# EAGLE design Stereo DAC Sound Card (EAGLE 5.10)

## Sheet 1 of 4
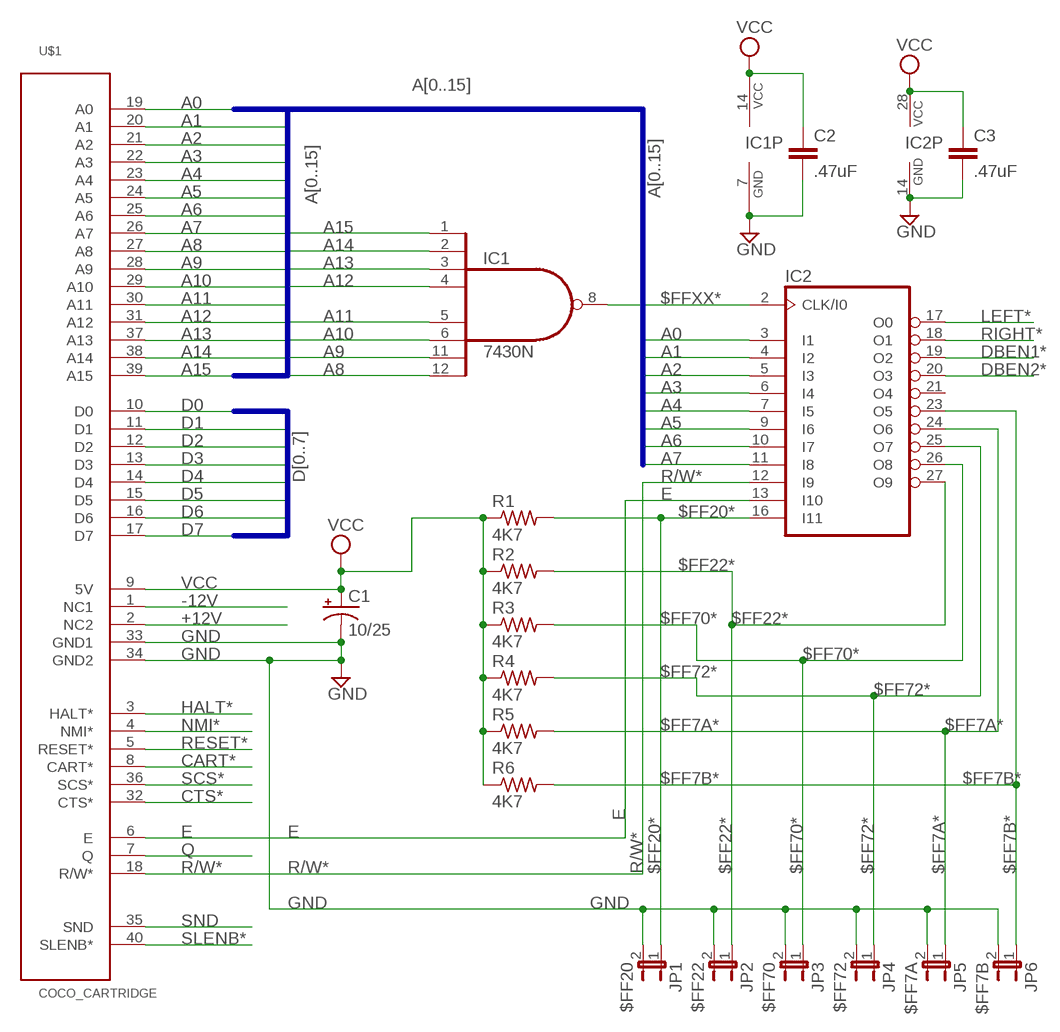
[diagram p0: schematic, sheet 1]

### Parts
C1  10/25  CAP_POLPTH1  [CPOL-RADIAL-100UF-25V]
C2  .47uF  CAPPTH2  [CAP-PTH-SMALL2]
C3  .47uF  CAPPTH2  [CAP-PTH-SMALL2]
IC1  7430N  [DIL14]
IC2  22V10L-5  [S28]
JP1  $FF20  JP1E  [JP1]
JP2  $FF22  JP1E  [JP1]
JP3  $FF70  JP1E  [JP1]
JP4  $FF72  JP1E  [JP1]
JP5  $FF7A  JP1E  [JP1]
JP6  $FF7B  JP1E  [JP1]
R1  4K7  R-US_0207/10  [0207/10]
R2  4K7  R-US_0207/10  [0207/10]
R3  4K7  R-US_0207/10  [0207/10]
R4  4K7  R-US_0207/10  [0207/10]
R5  4K7  R-US_0207/10  [0207/10]
R6  4K7  R-US_0207/10  [0207/10]
U$1  COCO_CARTRIDGE  SERIALTECH_COCO_CARTRIDGE  [SERIALTECH_EDGE40]

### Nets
$FF7A*: IC2.24(O6) JP5.1 R5.2
$FF7B*: IC2.23(O5) JP6.1 R6.2
$FF20*: IC2.16(I11) JP1.1 R1.2
$FF22*: IC2.27(O9) JP2.1 R2.2
$FF70*: IC2.26(O8) JP3.1 R3.2
$FF72*: IC2.25(O7) JP4.1 R4.2
$FFXX*: IC1.8(O) IC2.2(CLK/I0)
+12V [power]: U$1.2(NC2) ; also sheet 3
-12V [power]: U$1.1(NC1) ; also sheet 3
A0: IC2.3(I1) U$1.19(A0) ; also sheet 3
A1: IC2.4(I2) U$1.20(A1) ; also sheet 3
A2: IC2.5(I3) U$1.21(A2) ; also sheet 3
A3: IC2.6(I4) U$1.22(A3) ; also sheet 3
A4: IC2.7(I5) U$1.23(A4) ; also sheet 3
A5: IC2.9(I6) U$1.24(A5) ; also sheet 3
A6: IC2.10(I7) U$1.25(A6) ; also sheet 3
A7: IC2.11(I8) U$1.26(A7) ; also sheet 3
A8: IC1.12(I7) U$1.27(A8) ; also sheet 3
A9: IC1.11(I6) U$1.28(A9) ; also sheet 3
A10: IC1.6(I5) U$1.29(A10) ; also sheet 3
A11: IC1.5(I4) U$1.30(A11) ; also sheet 3
A12: IC1.4(I3) U$1.31(A12) ; also sheet 3
A13: IC1.3(I2) U$1.37(A13) ; also sheet 3
A14: IC1.2(I1) U$1.38(A14) ; also sheet 3
A15: IC1.1(I0) U$1.39(A15) ; also sheet 3
CART*: U$1.8(CART*) ; also sheet 3
CTS*: U$1.32(CTS*) ; also sheet 3
D0: U$1.10(D0) ; also sheet 2,3
D1: U$1.11(D1) ; also sheet 2,3
D2: U$1.12(D2) ; also sheet 2,3
D3: U$1.13(D3) ; also sheet 2,3
D4: U$1.14(D4) ; also sheet 2,3
D5: U$1.15(D5) ; also sheet 2,3
D6: U$1.16(D6) ; also sheet 2,3
D7: U$1.17(D7) ; also sheet 2,3
DBEN1*: IC2.19(O2) ; also sheet 2
DBEN2*: IC2.20(O3) ; also sheet 2
E: IC2.13(I10) U$1.6(E) ; also sheet 3
GND [power]: C1.2(-) C2.2 C3.2 IC1.7(GND) IC2.14(GND) JP1.2 JP2.2 JP3.2 JP4.2 JP5.2 JP6.2 U$1.33(GND1) U$1.34(GND2) ; also sheet 2,3,4
HALT*: U$1.3(HALT*) ; also sheet 3
LEFT*: IC2.17(O0) ; also sheet 4
NMI*: U$1.4(NMI*) ; also sheet 3
Q: U$1.7(Q) ; also sheet 3
R/W*: IC2.12(I9) U$1.18(R/W*) ; also sheet 3
RESET*: U$1.5(RESET*) ; also sheet 3
RIGHT*: IC2.18(O1) ; also sheet 4
SCS*: U$1.36(SCS*) ; also sheet 3
SLENB*: U$1.40(SLENB*) ; also sheet 3
SND: U$1.35(SND) ; also sheet 3
VCC [power]: C1.1(+) C2.1 C3.1 IC1.14(VCC) IC2.28(VCC) R1.1 R2.1 R3.1 R4.1 R5.1 R6.1 U$1.9(5V) ; also sheet 2,3,4
Unconnected: IC2.21(O4)

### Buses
A[0..15]
D[0..7]

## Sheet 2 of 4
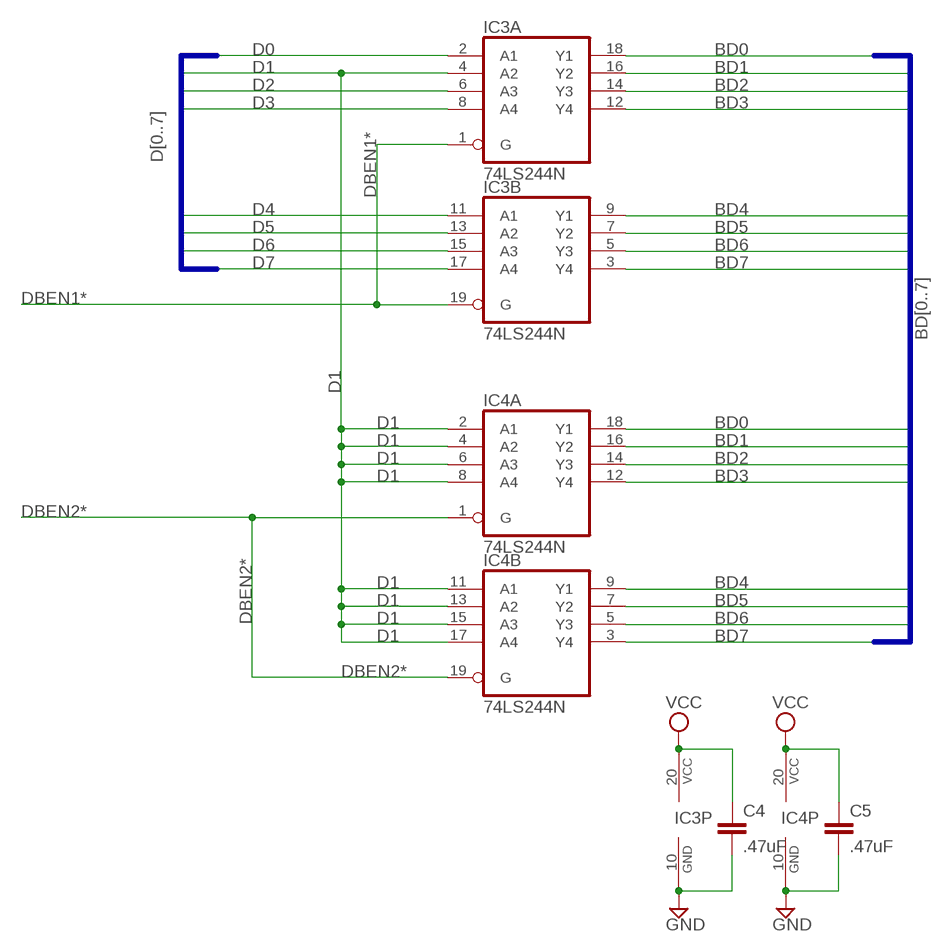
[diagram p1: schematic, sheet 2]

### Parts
C4  .47uF  CAPPTH2  [CAP-PTH-SMALL2]
C5  .47uF  CAPPTH2  [CAP-PTH-SMALL2]
IC3  74LS244N  [DIL20]
IC4  74LS244N  [DIL20]

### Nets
BD0: IC3.18(A:Y1) IC4.18(A:Y1) ; also sheet 4
BD1: IC3.16(A:Y2) IC4.16(A:Y2) ; also sheet 4
BD2: IC3.14(A:Y3) IC4.14(A:Y3) ; also sheet 4
BD3: IC3.12(A:Y4) IC4.12(A:Y4) ; also sheet 4
BD4: IC3.9(B:Y1) IC4.9(B:Y1) ; also sheet 4
BD5: IC3.7(B:Y2) IC4.7(B:Y2) ; also sheet 4
BD6: IC3.5(B:Y3) IC4.5(B:Y3) ; also sheet 4
BD7: IC3.3(B:Y4) IC4.3(B:Y4) ; also sheet 4
D0: IC3.2(A:A1) ; also sheet 1,3
D1: IC3.4(A:A2) IC4.2(A:A1) IC4.4(A:A2) IC4.6(A:A3) IC4.8(A:A4) IC4.11(B:A1) IC4.13(B:A2) IC4.15(B:A3) IC4.17(B:A4) ; also sheet 1,3
D2: IC3.6(A:A3) ; also sheet 1,3
D3: IC3.8(A:A4) ; also sheet 1,3
D4: IC3.11(B:A1) ; also sheet 1,3
D5: IC3.13(B:A2) ; also sheet 1,3
D6: IC3.15(B:A3) ; also sheet 1,3
D7: IC3.17(B:A4) ; also sheet 1,3
DBEN1*: IC3.1(A:G) IC3.19(B:G) ; also sheet 1
DBEN2*: IC4.1(A:G) IC4.19(B:G) ; also sheet 1
GND [power]: C4.2 C5.2 IC3.10(P:GND) IC4.10(P:GND) ; also sheet 1,3,4
VCC [power]: C4.1 C5.1 IC3.20(P:VCC) IC4.20(P:VCC) ; also sheet 1,3,4

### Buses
D[0..7]
BD[0..7]

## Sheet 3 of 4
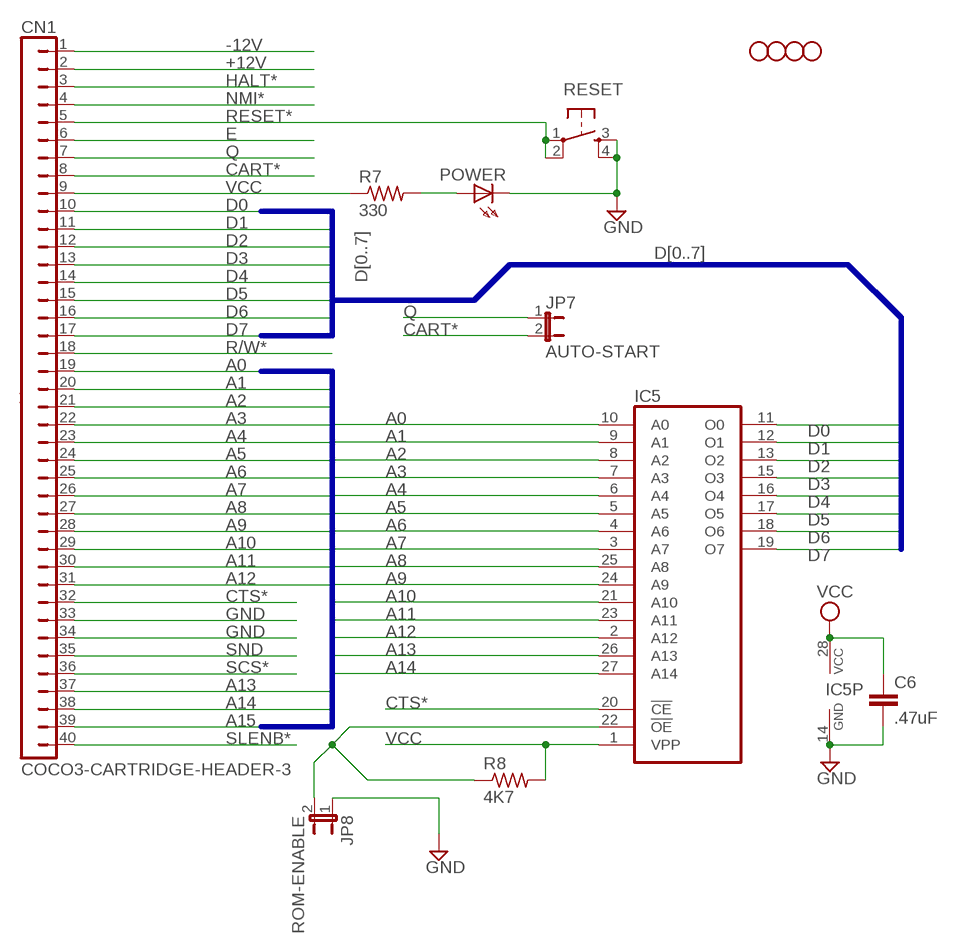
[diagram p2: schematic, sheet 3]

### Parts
C6  .47uF  CAPPTH2  [CAP-PTH-SMALL2]
CN1  COCO3-CARTRIDGE-HEADER-3  [HEADER-40]
IC5  27256  [DIL28]
JP7  AUTO-START  JP1E  [JP1]
JP8  ROM-ENABLE  JP1E  [JP1]
POWER  LED_LED5MM  [LED_LED5MM]
R7  330  R-US_0207/10  [0207/10]
R8  4K7  R-US_0207/10  [0207/10]
RESET  RESET  TAC_SWITCHPTH  [TACTILE-PTH]
U$2  SPARKFUN_STAND-OFF  [SPARKFUN_STAND-OFF]
U$3  SPARKFUN_STAND-OFF  [SPARKFUN_STAND-OFF]
U$4  SPARKFUN_STAND-OFF  [SPARKFUN_STAND-OFF]
U$5  SPARKFUN_STAND-OFF  [SPARKFUN_STAND-OFF]

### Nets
+12V [power]: CN1.2 ; also sheet 1
-12V [power]: CN1.1 ; also sheet 1
A0: CN1.19 IC5.10(A0) ; also sheet 1
A1: CN1.20 IC5.9(A1) ; also sheet 1
A2: CN1.21 IC5.8(A2) ; also sheet 1
A3: CN1.22 IC5.7(A3) ; also sheet 1
A4: CN1.23 IC5.6(A4) ; also sheet 1
A5: CN1.24 IC5.5(A5) ; also sheet 1
A6: CN1.25 IC5.4(A6) ; also sheet 1
A7: CN1.26 IC5.3(A7) ; also sheet 1
A8: CN1.27 IC5.25(A8) ; also sheet 1
A9: CN1.28 IC5.24(A9) ; also sheet 1
A10: CN1.29 IC5.21(A10) ; also sheet 1
A11: CN1.30 IC5.23(A11) ; also sheet 1
A12: CN1.31 IC5.2(A12) ; also sheet 1
A13: CN1.37 IC5.26(A13) ; also sheet 1
A14: CN1.38 IC5.27(A14) ; also sheet 1
A15: CN1.39 ; also sheet 1
CART*: CN1.8 JP7.2 ; also sheet 1
CTS*: CN1.32 IC5.20(!CE) ; also sheet 1
D0: CN1.10 IC5.11(O0) ; also sheet 1,2
D1: CN1.11 IC5.12(O1) ; also sheet 1,2
D2: CN1.12 IC5.13(O2) ; also sheet 1,2
D3: CN1.13 IC5.15(O3) ; also sheet 1,2
D4: CN1.14 IC5.16(O4) ; also sheet 1,2
D5: CN1.15 IC5.17(O5) ; also sheet 1,2
D6: CN1.16 IC5.18(O6) ; also sheet 1,2
D7: CN1.17 IC5.19(O7) ; also sheet 1,2
E: CN1.6 ; also sheet 1
GND [power]: C6.2 CN1.33 CN1.34 IC5.14(GND) JP8.1 POWER.K(C) RESET.3 RESET.4 ; also sheet 1,2,4
HALT*: CN1.3 ; also sheet 1
N$1: POWER.A R7.2
N$2: IC5.22(!OE) JP8.2 R8.1
NMI*: CN1.4 ; also sheet 1
Q: CN1.7 JP7.1 ; also sheet 1
R/W*: CN1.18 ; also sheet 1
RESET*: CN1.5 RESET.1 RESET.2 ; also sheet 1
SCS*: CN1.36 ; also sheet 1
SLENB*: CN1.40 ; also sheet 1
SND: CN1.35 ; also sheet 1
VCC [power]: C6.1 CN1.9 IC5.1(VPP) IC5.28(VCC) R7.1 R8.2 ; also sheet 1,2,4

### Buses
A[0..15]
D[0..7]

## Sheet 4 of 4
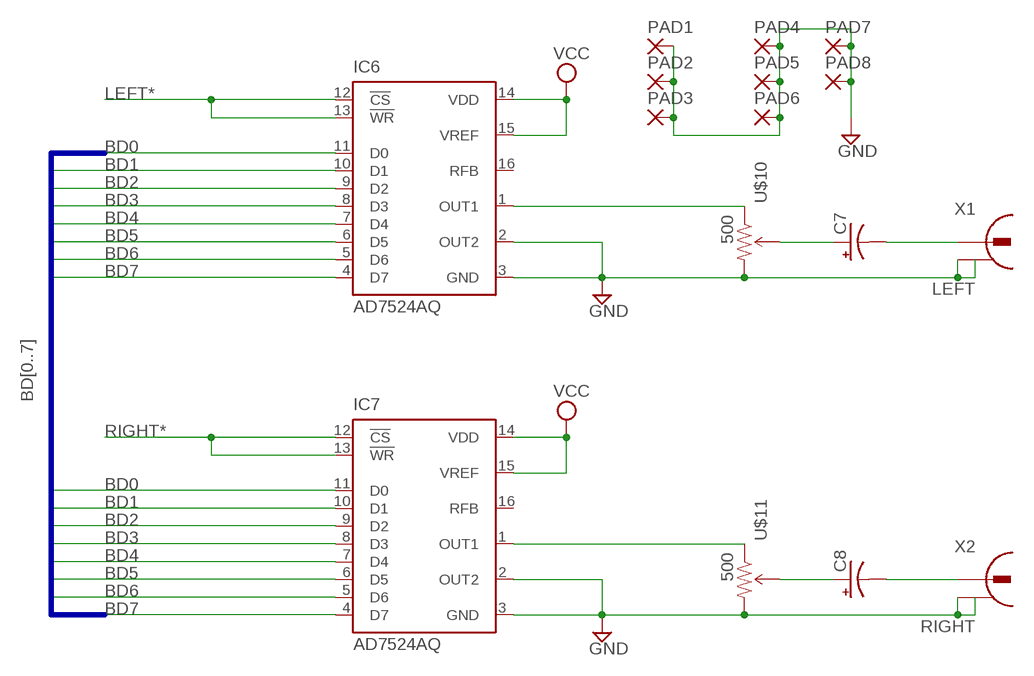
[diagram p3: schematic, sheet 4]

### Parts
C7  CAP_POLPTH2  [CPOL-RADIAL-10UF-25V]
C8  CAP_POLPTH2  [CPOL-RADIAL-10UF-25V]
IC6  AD7524AQ  [DIL16]
IC7  AD7524AQ  [DIL16]
PAD1  3,81/1,4  [3,81/1,4]
PAD2  3,81/1,4  [3,81/1,4]
PAD3  3,81/1,4  [3,81/1,4]
PAD4  3,81/1,4  [3,81/1,4]
PAD5  3,81/1,4  [3,81/1,4]
PAD6  3,81/1,4  [3,81/1,4]
PAD7  3,81/1,4  [3,81/1,4]
PAD8  3,81/1,4  [3,81/1,4]
U$10  500  TRIMPOT  [3362U-2]
U$11  500  TRIMPOT  [3362U-2]
X1  LEFT  736880-49  [736880-49]
X2  RIGHT  736880-49  [736880-49]

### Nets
BD0: IC6.11(D0) IC7.11(D0) ; also sheet 2
BD1: IC6.10(D1) IC7.10(D1) ; also sheet 2
BD2: IC6.9(D2) IC7.9(D2) ; also sheet 2
BD3: IC6.8(D3) IC7.8(D3) ; also sheet 2
BD4: IC6.7(D4) IC7.7(D4) ; also sheet 2
BD5: IC6.6(D5) IC7.6(D5) ; also sheet 2
BD6: IC6.5(D6) IC7.5(D6) ; also sheet 2
BD7: IC6.4(D7) IC7.4(D7) ; also sheet 2
GND [power]: IC6.2(OUT2) IC6.3(GND) IC7.2(OUT2) IC7.3(GND) PAD1.1(P) PAD2.1(P) PAD3.1(P) PAD4.1(P) PAD5.1(P) PAD6.1(P) PAD7.1(P) PAD8.1(P) U$10.3(CW) U$11.3(CW) X1.2 X1.2@2 X2.2 X2.2@2 ; also sheet 1,2,3
LEFT*: IC6.12(!CS) IC6.13(!WR) ; also sheet 1
N$3: IC7.1(OUT1) U$11.1(CCW)
N$4: C8.1(+) U$11.2(WIPER)
N$5: IC6.1(OUT1) U$10.1(CCW)
N$6: C8.2(-) X2.1
N$7: C7.1(+) U$10.2(WIPER)
N$8: C7.2(-) X1.1
RIGHT*: IC7.12(!CS) IC7.13(!WR) ; also sheet 1
VCC [power]: IC6.14(VDD) IC6.15(VREF) IC7.14(VDD) IC7.15(VREF) ; also sheet 1,2,3
Unconnected: IC6.16(RFB) IC7.16(RFB)

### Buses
BD[0..7]

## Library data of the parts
C1 C7 C8 = SparkFunEagle-6-6-07:CAP_POL: Capacitor Polarized
C2-C6 = SparkFunEagle-6-6-07:CAP: Capacitor
CN1 = GIMEchip:COCO3-CARTRIDGE-HEADER-3
IC1 = 74xx-us:74*30: 8-input NAND gate
IC2 = pld-intel:22V10L-5: PLD
IC3 IC4 = 74xx-us:74*244: Octal BUFFER and LINE DRIVER, 3-state
IC5 = memory:27256: MEMORY
IC6 IC7 = analog-devices:AD7524*: 8-Bit Buffered Multiplying DAC Source: http://www.analog.com/UploadedFiles/Data_Sheets/888358036ad7524.pdf
JP1-JP8 = jumper:JP1E: JUMPER
PAD1-PAD8 = wirepad:3,81/1,4: THROUGH-HOLE PAD
POWER = ZX15-004:LED_LED: LED
R1-R8 = rcl:R-US_: RESISTOR, American symbol
RESET = SparkFunEagle-6-6-07:TAC_SWITCH: Momentary Switch Button commonly used for reset or general input. Spark Fun Electronics SKU : COM-00097
U$1 = FDC:SERIALTECH_COCO_CARTRIDGE
U$2-U$5 = FDC:SPARKFUN_STAND-OFF: Stand Off
U$10 U$11 = SparkFun:TRIMPOT
X1 X2 = con-conrad:736880-49: Cinch Connector ( RCA Jack )

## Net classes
0 default: width 0.203 mm, clearance 0.203 mm
1 power: width 0.762 mm, clearance 0.381 mm

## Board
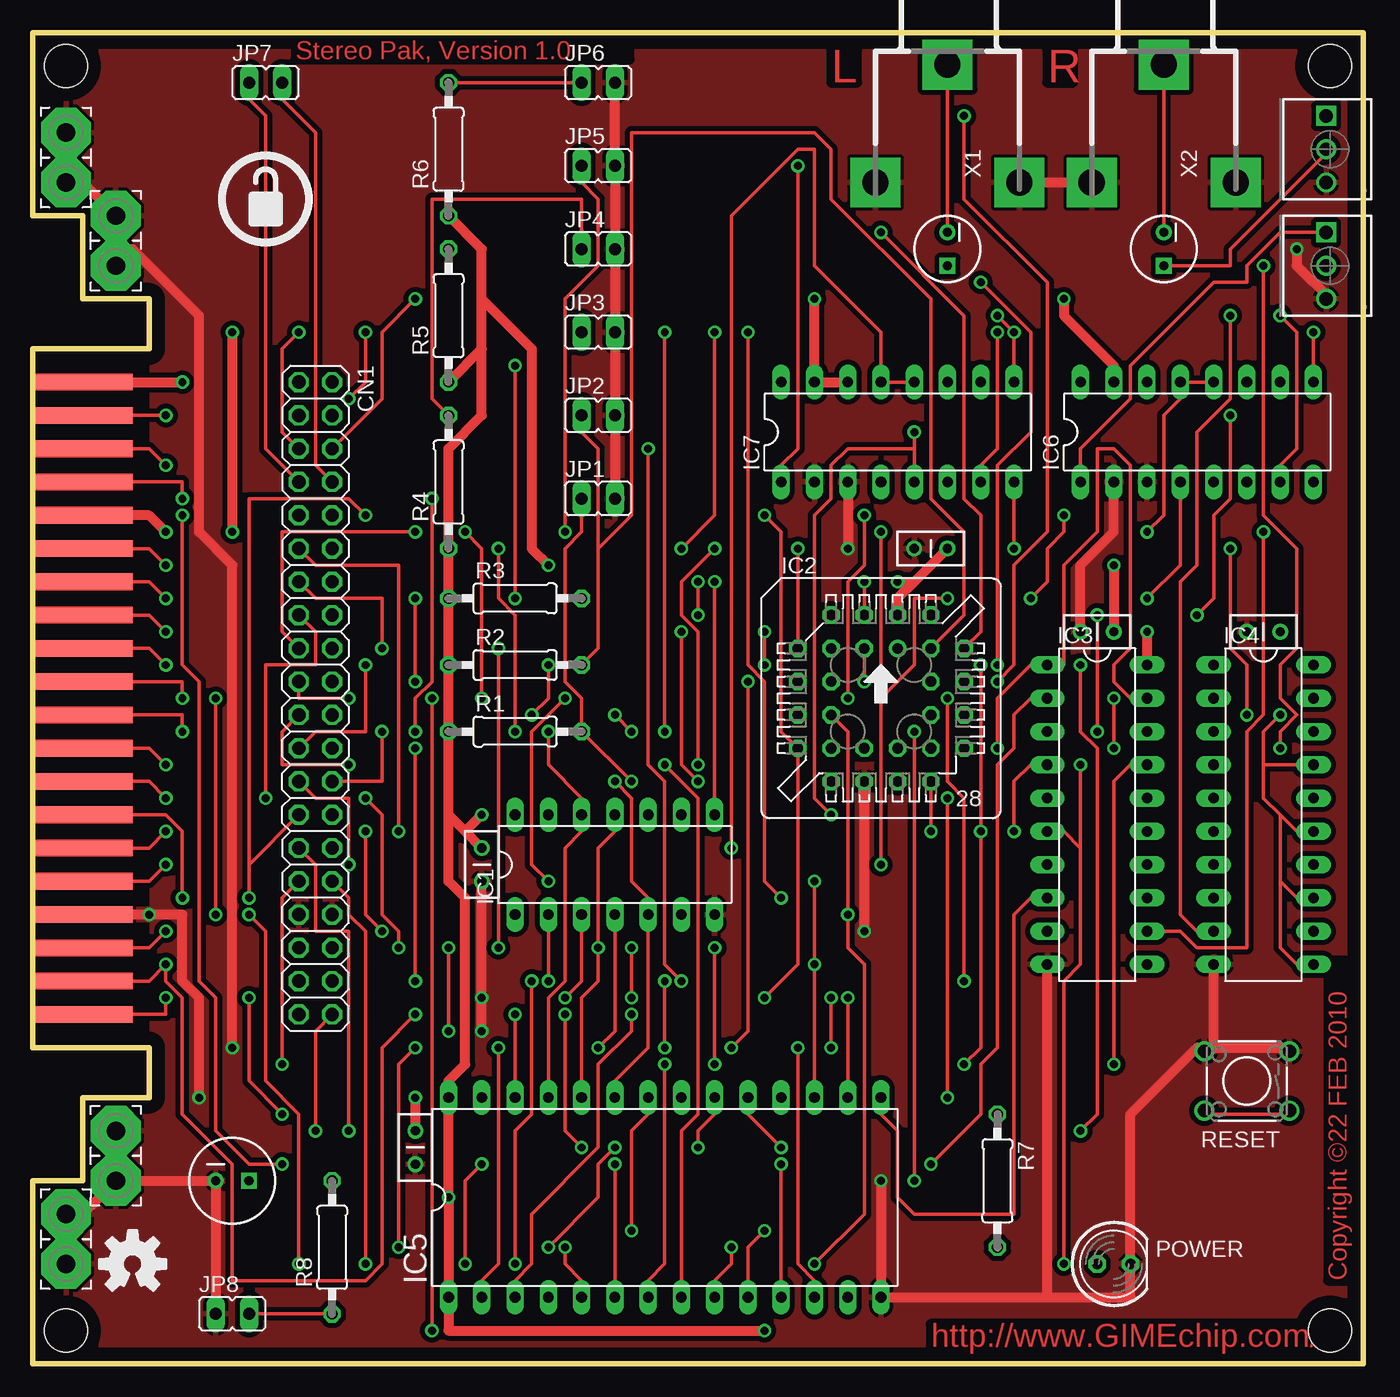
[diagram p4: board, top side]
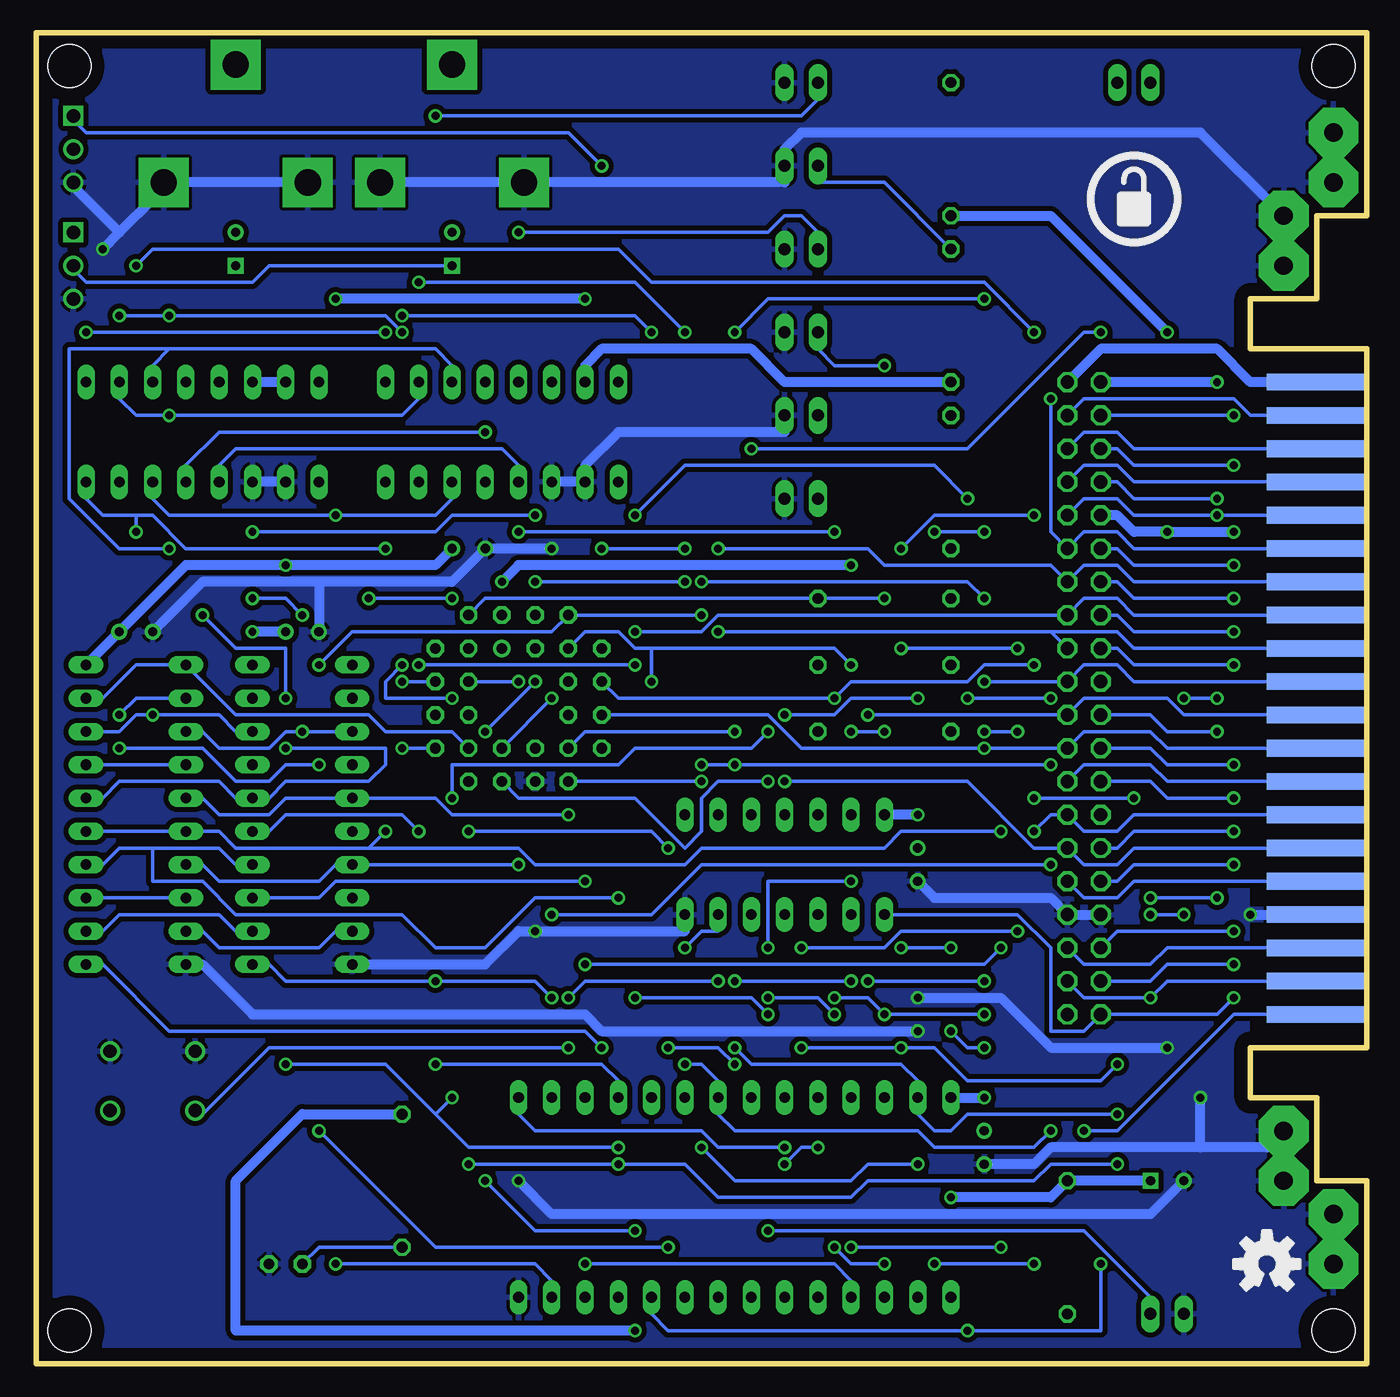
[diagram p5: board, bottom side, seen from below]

Size 101.6 x 101.6 mm. Coordinates in mm from the lower left corner, seen from the top.
Outline: 8.89,24.13 0,24.13 0,77.47 8.89,77.47 8.89,81.28 3.81,81.28 3.81,87.63 0,87.63 0,101.6 101.6,101.6 101.6,0 0,0 0,13.97 3.81,13.97 3.81,20.32 8.89,20.32 8.89,24.13
Copper layers (1*16): Top 0.035mm / dielectric 1.5mm / Bottom 0.035mm
Design rules "default": minimum track width 10mil, minimum drill 24mil, track to track 8mil, track to pad 8mil, pad to pad 8mil, via to via 8mil, smd to smd 8mil, copper to edge 40mil, drill to drill 8mil, minimum pad ring 10mil, minimum via ring 8mil, stop-mask expansion 4mil, vias tented up to drill 0mil, thermal gap 10mil

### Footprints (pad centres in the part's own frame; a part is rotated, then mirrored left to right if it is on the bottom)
CPOL-RADIAL-100UF-25V = drill 0.7 square: 1 1.27,0 | drill 0.7 round: 2 -1.27,0
CAP-PTH-SMALL2 = drill 0.7 round: 1 0,0; 2 2.54,0
CPOL-RADIAL-10UF-25V = drill 0.7 square: 1 1.27,0 | drill 0.7 round: 2 -1.27,0
HEADER-40 = drill 1.016 octagon: 1 -1.27,24.13; 2 1.27,24.13; 3 -1.27,21.59; 4 1.27,21.59; 5 -1.27,19.05; 6 1.27,19.05; 7 -1.27,16.51; 8 1.27,16.51; 9 -1.27,13.97; 10 1.27,13.97; 11 -1.27,11.43; 12 1.27,11.43; 13 -1.27,8.89; 14 1.27,8.89; 15 -1.27,6.35; 16 1.27,6.35; 17 -1.27,3.81; 18 1.27,3.81; 19 -1.27,1.27; 20 1.27,1.27; 21 -1.27,-1.27; 22 1.27,-1.27; 23 -1.27,-3.81; 24 1.27,-3.81; 25 -1.27,-6.35; 26 1.27,-6.35; 27 -1.27,-8.89; 28 1.27,-8.89; 29 -1.27,-11.43; 30 1.27,-11.43; 31 -1.27,-13.97; 32 1.27,-13.97; 33 -1.27,-16.51; 34 1.27,-16.51; 35 -1.27,-19.05; 36 1.27,-19.05; 37 -1.27,-21.59; 38 1.27,-21.59; 39 -1.27,-24.13; 40 1.27,-24.13
DIL14 = drill 0.813 long: 1 -7.62,-3.81; 2 -5.08,-3.81; 3 -2.54,-3.81; 4 0,-3.81; 5 2.54,-3.81; 6 5.08,-3.81; 7 7.62,-3.81; 8 7.62,3.81; 9 5.08,3.81; 10 2.54,3.81; 11 0,3.81; 12 -2.54,3.81; 13 -5.08,3.81; 14 -7.62,3.81
S28 = drill 0.813 round: 1 1.27,3.81 | drill 0.813 octagon: 2 -1.27,6.35; 3 -1.27,3.81; 4 -3.81,6.35; 5 -6.35,3.81; 6 -3.81,3.81; 7 -6.35,1.27; 8 -3.81,1.27; 9 -6.35,-1.27; 10 -3.81,-1.27; 11 -6.35,-3.81; 12 -3.81,-6.35; 13 -3.81,-3.81; 14 -1.27,-6.35; 15 -1.27,-3.81; 16 1.27,-6.35; 17 1.27,-3.81; 18 3.81,-6.35; 19 6.35,-3.81; 20 3.81,-3.81; 21 6.35,-1.27; 22 3.81,-1.27; 23 6.35,1.27; 24 3.81,1.27; 25 6.35,3.81; 26 3.81,6.35; 27 3.81,3.81; 28 1.27,6.35
DIL20 = drill 0.813 long: 1 -11.43,-3.81; 2 -8.89,-3.81; 3 -6.35,-3.81; 4 -3.81,-3.81; 5 -1.27,-3.81; 6 1.27,-3.81; 7 3.81,-3.81; 8 6.35,-3.81; 9 8.89,-3.81; 10 11.43,-3.81; 11 11.43,3.81; 12 8.89,3.81; 13 6.35,3.81; 14 3.81,3.81; 15 1.27,3.81; 16 -1.27,3.81; 17 -3.81,3.81; 18 -6.35,3.81; 19 -8.89,3.81; 20 -11.43,3.81
DIL28 = drill 0.813 long: 1 -16.51,-7.62; 2 -13.97,-7.62; 3 -11.43,-7.62; 4 -8.89,-7.62; 5 -6.35,-7.62; 6 -3.81,-7.62; 7 -1.27,-7.62; 8 1.27,-7.62; 9 3.81,-7.62; 10 6.35,-7.62; 11 8.89,-7.62; 12 11.43,-7.62; 13 13.97,-7.62; 14 16.51,-7.62; 15 16.51,7.62; 16 13.97,7.62; 17 11.43,7.62; 18 8.89,7.62; 19 6.35,7.62; 20 3.81,7.62; 21 1.27,7.62; 22 -1.27,7.62; 23 -3.81,7.62; 24 -6.35,7.62; 25 -8.89,7.62; 26 -11.43,7.62; 27 -13.97,7.62; 28 -16.51,7.62
DIL16 = drill 0.813 long: 1 -8.89,-3.81; 2 -6.35,-3.81; 3 -3.81,-3.81; 4 -1.27,-3.81; 5 1.27,-3.81; 6 3.81,-3.81; 7 6.35,-3.81; 8 8.89,-3.81; 9 8.89,3.81; 10 6.35,3.81; 11 3.81,3.81; 12 1.27,3.81; 13 -1.27,3.81; 14 -3.81,3.81; 15 -6.35,3.81; 16 -8.89,3.81
JP1 = drill 0.914 long: 1 0,-1.27; 2 0,1.27
3,81/1,4 = drill 1.397 pad 3.81 octagon: 1 0,0
LED_LED5MM = drill 0.813 octagon: A -1.27,0; K 1.27,0
0207/10 = drill 0.813 octagon: 1 -5.08,0; 2 5.08,0
TACTILE-PTH = drill 1.016 round: 1 -3.251,2.261; 2 3.251,2.261; 3 -3.251,-2.261; 4 3.251,-2.261
SERIALTECH_EDGE40 = smd 7.62 x 1.27: 1 0,24.13; 3 0,21.59; 5 0,19.05; 7 0,16.51; 9 0,13.97; 11 0,11.43; 13 0,8.89; 15 0,6.35; 17 0,3.81; 19 0,1.27; 21 0,-1.27; 23 0,-3.81; 25 0,-6.35; 27 0,-8.89; 29 0,-11.43; 31 0,-13.97; 33 0,-16.51; 35 0,-19.05; 37 0,-21.59; 39 0,-24.13 | smd 7.62 x 1.27 bottom: 2 0,24.13; 4 0,21.59; 6 0,19.05; 8 0,16.51; 10 0,13.97; 12 0,11.43; 14 0,8.89; 16 0,6.35; 18 0,3.81; 20 0,1.27; 22 0,-1.27; 24 0,-3.81; 26 0,-6.35; 28 0,-8.89; 30 0,-11.43; 32 0,-13.97; 34 0,-16.51; 36 0,-19.05; 38 0,-21.59; 40 0,-24.13
SPARKFUN_STAND-OFF = hole 3.302: 0,0
3362U-2 = drill 1.016 square: 1 -2.54,-0.305 | drill 1.016 round: 2 0,-0.305; 3 2.54,-0.305
736880-49 = drill 2 pad 3.81 square: 1 -3.92,0; 2 5.08,5.5; 2@2 5.08,-5.5

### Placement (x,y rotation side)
C1  15.24,13.97 0 top
C2  34.29,39.37 270 top
C3  69.85,62.23 180 top
C4  82.55,55.88 180 top
C5  95.25,55.88 180 top
C6  29.21,17.78 270 top
C7  69.85,85.09 270 top
C8  86.36,85.09 270 top
CN1  21.59,50.8 0 top
IC1  44.45,38.1 0 top
IC2  64.77,50.8 0 top
IC3  81.28,41.91 270 top
IC4  93.98,41.91 270 top
IC5  48.26,12.7 0 top
IC6  88.9,71.12 0 top
IC7  66.04,71.12 0 top
JP1  43.18,66.04 270 top
JP2  43.18,72.39 270 top
JP3  43.18,78.74 270 top
JP4  43.18,85.09 270 top
JP5  43.18,91.44 270 top
JP6  43.18,97.79 270 top
JP7  17.78,97.79 270 top
JP8  15.24,3.81 270 top
PAD1  2.54,93.98 270 top
PAD2  2.54,90.17 270 top
PAD3  6.35,87.63 270 top
PAD4  6.35,83.82 270 top
PAD5  6.35,17.78 270 top
PAD6  6.35,13.97 270 top
PAD7  2.54,11.43 270 top
PAD8  2.54,7.62 270 top
POWER  82.55,7.62 0 top
R1  36.83,48.26 0 top
R2  36.83,53.34 0 top
R3  36.83,58.42 0 top
R4  31.75,67.31 90 top
R5  31.75,80.01 90 top
R6  31.75,92.71 90 top
R7  73.66,13.97 270 top
R8  22.86,8.89 90 top
RESET  92.71,21.59 180 top
U$1  3.81,50.8 0 top
U$2  2.54,99.06 0 top
U$3  2.54,2.54 0 top
U$4  99.06,99.06 0 top
U$5  99.06,2.54 0 top
U$6  [OSHWLOGO_0.3]  17.78,88.9 0 top
U$7  [OSHWLOGO_0.3]  17.78,88.9 0 bottom
U$8  [OSHWLOGO_TOL_0.2]  7.62,7.62 0 top
U$9  [OSHWLOGO_TOL_0.2]  7.62,7.62 0 bottom
U$10  99.06,83.82 270 top
U$11  99.06,92.71 270 top
X1  69.85,95.25 270 top
X2  86.36,95.25 270 top

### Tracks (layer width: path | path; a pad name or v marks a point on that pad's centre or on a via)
$FF7A*  (via drill 0.61)
  Top 0.254: v64.77,63.5 v64.77,52.07 | v40.64,63.5 40.64,81.28 43.18,83.82 43.18,88.9 41.91,90.17 JP5.1
  Bottom 0.254: R5.2 36.83,90.17 41.91,90.17 JP5.1 | v64.77,52.07 IC2.24 | v40.64,63.5 v64.77,63.5
$FF7B*  (via drill 0.61)
  Top 0.254: JP6.1 R6.2 | v73.66,52.07 74.93,53.34 74.93,60.96 77.47,63.5 77.47,82.55 71.12,88.9 v71.12,95.25
  Bottom 0.254: IC2.23 v73.66,52.07 | v71.12,95.25 43.18,95.25 41.91,96.52 JP6.1
$FF20*  (via drill 0.61)
  Top 0.254: JP1.1 41.91,63.5 40.64,62.23 40.64,52.07 41.91,50.8 R1.2 v45.72,44.45
  Bottom 0.254: IC2.16 64.77,43.18 55.88,43.18 52.07,39.37 50.8,40.64 50.8,43.18 49.53,44.45 v45.72,44.45
$FF22*
  Top 0.254: R2.2 43.18,54.61 43.18,62.23 | 43.18,62.23 43.18,69.85 41.91,71.12 JP2.1 | IC2.27 71.12,57.15 71.12,63.5 68.58,66.04 68.58,81.28 60.96,88.9 60.96,92.71 59.69,93.98 45.72,93.98 45.72,64.77 43.18,62.23
$FF70*  (via drill 0.61)
  Top 0.254: v36.83,58.42 v36.83,76.2
  Bottom 0.254: IC2.26 67.31,58.42 R3.2 v36.83,58.42 | v36.83,76.2 40.64,76.2 41.91,77.47 JP3.1
$FF72*  (via drill 0.61)
  Top 0.254: IC2.25 72.39,55.88 72.39,64.77 71.12,66.04 71.12,80.01 v64.77,86.36 | R4.2 30.48,73.66 30.48,88.9 41.91,88.9 JP4.1
  Bottom 0.254: v64.77,86.36 45.72,86.36 44.45,87.63 43.18,87.63 41.91,86.36 JP4.1
$FFXX*  (via drill 0.61)
  Top 0.254: v63.5,59.69 IC2.2 | IC1.8 v52.07,59.69
  Bottom 0.254: v52.07,59.69 v63.5,59.69
+12V
  Bottom 0.762: CN1.2 20.32,77.47 11.43,77.47 8.89,74.93 U$1.2
-12V  (via drill 0.61)
  Top 0.762: U$1.1 v11.43,74.93
  Bottom 0.762: v11.43,74.93 CN1.1
A0  (via drill 0.61)
  Top 0.254: v30.48,2.54 v30.48,50.8 | v24.13,50.8 20.32,50.8 CN1.19 | v63.5,52.07 IC2.3 | v67.31,13.97 v67.31,48.26 | v55.88,10.16 54.61,8.89 IC5.10 | v11.43,50.8 11.43,52.07 U$1.19 | v13.97,34.29 v13.97,50.8 | v16.51,34.29 17.78,33.02 17.78,21.59 20.32,19.05 v20.32,7.62
  Bottom 0.254: v30.48,50.8 v24.13,50.8 | IC5.10 54.61,3.81 53.34,2.54 v30.48,2.54 20.32,2.54 v20.32,7.62 | v67.31,48.26 v63.5,52.07 | v67.31,13.97 63.5,10.16 v55.88,10.16 | v13.97,50.8 v11.43,50.8 | v16.51,34.29 v13.97,34.29
A1  (via drill 0.61)
  Top 0.254: v53.34,8.89 53.34,7.62 52.07,6.35 IC5.9 | v80.01,17.78 81.28,19.05 81.28,46.99 80.01,48.26 v80.01,53.34 | v29.21,52.07 v29.21,58.42 | v50.8,59.69 v50.8,57.15
  Bottom 0.254: U$1.20 17.78,52.07 19.05,53.34 21.59,53.34 CN1.20 v29.21,52.07 | v53.34,8.89 71.12,8.89 v80.01,17.78 | v80.01,53.34 77.47,55.88 62.23,55.88 IC2.4 v50.8,57.15 | v29.21,58.42 30.48,59.69 v50.8,59.69
A2  (via drill 0.61)
  Top 0.254: v48.26,45.72 50.8,43.18 50.8,19.05 49.53,17.78 IC5.8 | v24.13,45.72 19.05,45.72 19.05,48.26 CN1.21 | v58.42,62.23 IC2.5 | v52.07,62.23 49.53,59.69 49.53,57.15 50.8,55.88 v50.8,45.72 | v11.43,48.26 11.43,49.53 U$1.21
  Bottom 0.254: v24.13,45.72 v48.26,45.72 v50.8,45.72 | v52.07,62.23 v58.42,62.23 | v11.43,48.26 15.24,48.26 16.51,49.53 CN1.21
A3  (via drill 0.61)
  Top 0.254: v48.26,22.86 48.26,7.62 46.99,6.35 IC5.7 | v53.34,24.13 54.61,25.4 v54.61,52.07 | v38.1,49.53 39.37,50.8 v39.37,53.34
  Bottom 0.254: U$1.22 13.97,49.53 15.24,50.8 21.59,50.8 CN1.22 v38.1,49.53 | v48.26,22.86 49.53,24.13 v53.34,24.13 | v54.61,52.07 54.61,54.61 | 54.61,54.61 55.88,54.61 57.15,55.88 59.69,55.88 IC2.6 | v39.37,53.34 40.64,54.61 54.61,54.61
A4  (via drill 0.61)
  Top 0.254: v10.16,45.72 8.89,46.99 U$1.23 | v41.91,16.51 40.64,17.78 v40.64,26.67 | v45.72,27.94 v45.72,31.75 | v39.37,36.83 38.1,38.1 38.1,48.26 v40.64,50.8 | IC5.6 v44.45,15.24 | CN1.23 21.59,48.26 25.4,48.26 v25.4,53.34
  Bottom 0.254: CN1.23 16.51,46.99 15.24,45.72 v10.16,45.72 | v44.45,15.24 43.18,16.51 v41.91,16.51 | v40.64,26.67 41.91,27.94 v45.72,27.94 | v45.72,31.75 45.72,36.83 v39.37,36.83 | IC2.7 57.15,50.8 v40.64,50.8 39.37,52.07 30.48,52.07 29.21,53.34 v25.4,53.34
A5  (via drill 0.61)
  Top 0.254: v40.64,8.89 40.64,7.62 41.91,6.35 IC5.5 | v36.83,7.62 36.83,17.78 38.1,19.05 v38.1,29.21 | v29.21,29.21 v29.21,46.99
  Bottom 0.254: v40.64,8.89 39.37,7.62 v36.83,7.62 | v38.1,29.21 v29.21,29.21 | IC2.9 45.72,49.53 43.18,46.99 v29.21,46.99 CN1.24 21.59,48.26 16.51,48.26 15.24,46.99 U$1.24
A6  (via drill 0.61)
  Top 0.254: v10.16,43.18 8.89,44.45 U$1.25 | v59.69,7.62 63.5,11.43 63.5,30.48 62.23,31.75 v62.23,34.29 62.23,48.26 IC2.10 | CN1.25 21.59,43.18 24.13,43.18 v24.13,38.1
  Bottom 0.254: CN1.25 16.51,44.45 15.24,43.18 v10.16,43.18 | v59.69,7.62 40.64,7.62 39.37,6.35 IC5.4 | v24.13,38.1 50.8,38.1 54.61,34.29 v62.23,34.29
A7  (via drill 0.61)
  Top 0.254: v45.72,26.67 45.72,25.4 43.18,22.86 43.18,16.51 38.1,11.43 38.1,7.62 36.83,6.35 IC5.3 | v55.88,27.94 58.42,30.48 IC2.11 57.15,48.26 57.15,63.5 v55.88,64.77 | CN1.26 26.67,44.45 v26.67,48.26 | v29.21,48.26 29.21,50.8 30.48,52.07 v30.48,66.04
  Bottom 0.254: CN1.26 21.59,45.72 16.51,45.72 15.24,44.45 U$1.26 | v45.72,26.67 46.99,27.94 v55.88,27.94 | v29.21,48.26 v26.67,48.26 | v30.48,66.04 33.02,68.58 52.07,68.58 v55.88,64.77
A8  (via drill 0.61)
  Top 0.254: IC5.25 39.37,27.94 40.64,29.21 40.64,39.37 41.91,40.64 IC1.12 41.91,43.18 39.37,45.72 v39.37,48.26 | 16.51,38.1 CN1.27 | v16.51,35.56 16.51,38.1 | v11.43,35.56 11.43,40.64 10.16,41.91 U$1.27 | v36.83,48.26 36.83,57.15 35.56,58.42 v35.56,62.23 | v25.4,64.77 24.13,66.04 16.51,66.04 16.51,38.1
  Bottom 0.254: v11.43,35.56 v16.51,35.56 | v36.83,48.26 v39.37,48.26 | v35.56,62.23 33.02,64.77 v25.4,64.77
A9  (via drill 0.61)
  Top 0.254: IC5.24 41.91,27.94 43.18,29.21 v43.18,31.75 43.18,39.37 44.45,40.64 IC1.11 | v26.67,33.02 25.4,34.29 v25.4,40.64
  Bottom 0.254: U$1.28 17.78,41.91 19.05,40.64 21.59,40.64 CN1.28 24.13,41.91 v25.4,40.64 | v43.18,31.75 36.83,31.75 35.56,33.02 v26.67,33.02
A10  (via drill 0.61)
  Top 0.254: v52.07,22.86 v52.07,31.75 | v10.16,40.64 8.89,39.37 U$1.29 | v24.13,17.78 24.13,33.02 21.59,33.02 21.59,38.1 CN1.29
  Bottom 0.254: v52.07,22.86 50.8,22.86 49.53,21.59 IC5.21 49.53,19.05 48.26,17.78 34.29,17.78 33.02,16.51 25.4,16.51 v24.13,17.78 | v52.07,31.75 50.8,33.02 49.53,33.02 IC1.6 | CN1.29 19.05,39.37 17.78,40.64 v10.16,40.64
A11  (via drill 0.61)
  Top 0.254: IC5.23 44.45,21.59 46.99,24.13 IC1.5 46.99,35.56 45.72,36.83 45.72,43.18 v44.45,44.45
  Bottom 0.254: U$1.30 17.78,39.37 19.05,38.1 21.59,38.1 CN1.30 25.4,39.37 30.48,44.45 v44.45,44.45
A12  (via drill 0.61)
  Top 0.254: v10.16,38.1 8.89,36.83 U$1.31 | v35.56,24.13 35.56,7.62 34.29,6.35 IC5.2 | v43.18,24.13 44.45,25.4 IC1.4 | CN1.31 19.05,35.56 v19.05,22.86
  Bottom 0.254: CN1.31 19.05,36.83 17.78,38.1 v10.16,38.1 | v43.18,24.13 v35.56,24.13 33.02,24.13 30.48,21.59 20.32,21.59 v19.05,22.86
A13  (via drill 0.61)
  Top 0.254: v40.64,27.94 41.91,29.21 IC1.3 | v36.83,26.67 IC5.26 | U$1.37 8.89,29.21 v10.16,30.48 10.16,29.21 11.43,27.94 11.43,19.05 15.24,15.24 15.24,6.35 25.4,6.35 26.67,7.62 26.67,24.13 v29.21,26.67
  Bottom 0.254: v40.64,27.94 38.1,27.94 v36.83,26.67 v29.21,26.67 | CN1.37 16.51,29.21 15.24,30.48 v10.16,30.48
A14  (via drill 0.61)
  Top 0.254: v19.05,19.05 16.51,21.59 v16.51,27.94 | v48.26,24.13 v48.26,29.21 | v39.37,29.21 IC1.2
  Bottom 0.254: v19.05,19.05 30.48,19.05 31.75,17.78 33.02,17.78 34.29,19.05 IC5.27 34.29,21.59 35.56,22.86 46.99,22.86 v48.26,24.13 | U$1.38 15.24,29.21 v16.51,27.94 21.59,27.94 CN1.38 | v48.26,29.21 v39.37,29.21
A15  (via drill 0.61)
  Top 0.254: v10.16,27.94 10.16,26.67 U$1.39
  Bottom 0.254: IC1.1 26.67,34.29 24.13,31.75 24.13,25.4 21.59,25.4 CN1.39 11.43,26.67 v10.16,27.94
BD0  (via drill 0.61)
  Top 0.254: v92.71,49.53 92.71,53.34 91.44,54.61 v91.44,62.23
  Bottom 0.254: IC3.18 86.36,48.26 87.63,49.53 v92.71,49.53 93.98,49.53 95.25,48.26 IC4.18 | 91.44,77.47 71.12,77.47 69.85,76.2 IC7.11 | 91.44,77.47 92.71,76.2 IC6.11 | v91.44,62.23 95.25,62.23 99.06,66.04 99.06,77.47 91.44,77.47
BD1  (via drill 0.61)
  Top 0.254: v82.55,46.99 v82.55,50.8 | v88.9,57.15 90.17,58.42 90.17,64.77 91.44,66.04 v91.44,72.39
  Bottom 0.254: IC4.16 96.52,43.18 95.25,44.45 87.63,44.45 86.36,43.18 IC3.16 83.82,43.18 82.55,44.45 76.2,44.45 74.93,45.72 74.93,46.99 v82.55,46.99 | IC7.10 72.39,73.66 73.66,72.39 v91.44,72.39 93.98,72.39 95.25,73.66 IC6.10 | v82.55,50.8 82.55,54.61 86.36,54.61 v88.9,57.15
BD2  (via drill 0.61)
  Top 0.254: IC7.9 v74.93,78.74 v73.66,80.01 | v97.79,78.74 IC6.9 | v57.15,35.56 55.88,36.83 55.88,52.07 54.61,53.34 v54.61,78.74
  Bottom 0.254: 92.71,39.37 95.25,39.37 96.52,38.1 IC4.14 | 92.71,39.37 87.63,39.37 86.36,38.1 IC3.14 | v74.93,78.74 v97.79,78.74 | 92.71,39.37 92.71,36.83 88.9,36.83 86.36,34.29 73.66,34.29 71.12,31.75 67.31,31.75 63.5,35.56 v57.15,35.56 | v54.61,78.74 55.88,80.01 v73.66,80.01
BD3  (via drill 0.61)
  Top 0.254: v74.93,62.23 IC7.8 | v93.98,63.5 93.98,49.53 92.71,48.26 92.71,31.75 88.9,31.75 87.63,33.02 IC3.12
  Bottom 0.254: IC3.12 86.36,33.02 87.63,34.29 95.25,34.29 96.52,33.02 IC4.12 | v74.93,62.23 90.17,62.23 92.71,64.77 93.98,64.77 | 93.98,64.77 96.52,64.77 97.79,66.04 IC6.8 | v93.98,63.5 93.98,64.77
BD4  (via drill 0.61)
  Top 0.254: v73.66,78.74 73.66,69.85 72.39,68.58 IC7.7 | v95.25,80.01 96.52,78.74 96.52,69.85 95.25,68.58 IC6.7 | v91.44,80.01 91.44,73.66 88.9,71.12 88.9,60.96 87.63,59.69 87.63,34.29 88.9,33.02 IC4.9
  Bottom 0.254: IC3.9 78.74,33.02 80.01,31.75 87.63,31.75 88.9,33.02 IC4.9 | v73.66,78.74 74.93,80.01 v91.44,80.01 v95.25,80.01
BD5  (via drill 0.61)
  Top 0.254: v64.77,38.1 64.77,50.8 67.31,53.34 67.31,58.42 v69.85,58.42 | v76.2,58.42 77.47,59.69 77.47,62.23 78.74,63.5 v78.74,64.77
  Bottom 0.254: IC4.7 88.9,38.1 87.63,36.83 80.01,36.83 78.74,38.1 IC3.7 v64.77,38.1 | IC7.6 69.85,66.04 71.12,64.77 v78.74,64.77 91.44,64.77 92.71,66.04 IC6.6 | v69.85,58.42 v76.2,58.42
BD6  (via drill 0.61)
  Top 0.254: 67.31,69.85 v67.31,71.12 | 67.31,69.85 IC7.5 | v60.96,41.91 59.69,43.18 59.69,64.77 60.96,66.04 60.96,68.58 62.23,69.85 67.31,69.85
  Bottom 0.254: IC4.5 88.9,43.18 87.63,41.91 83.82,41.91 82.55,43.18 IC3.5 71.12,43.18 69.85,41.91 v60.96,41.91 | v67.31,71.12 87.63,71.12 90.17,68.58 IC6.5
BD7  (via drill 0.61)
  Top 0.254: v81.28,48.26 v81.28,57.15 | v85.09,58.42 87.63,60.96 IC6.4
  Bottom 0.254: IC3.3 v81.28,48.26 82.55,48.26 83.82,46.99 87.63,46.99 88.9,48.26 IC4.3 | IC7.4 64.77,68.58 66.04,69.85 86.36,69.85 87.63,68.58 IC6.4 | v81.28,57.15 82.55,58.42 v85.09,58.42
CART*
  Top 0.254: CN1.8 21.59,68.58 21.59,93.98 19.05,96.52 JP7.2
  Bottom 0.254: CN1.8 21.59,68.58 19.05,68.58 17.78,67.31 U$1.8
CTS*  (via drill 0.61)
  Top 0.254: v50.8,16.51 50.8,17.78 52.07,19.05 IC5.20 | v34.29,15.24 33.02,13.97 v33.02,7.62 | v25.4,7.62 25.4,33.02 24.13,34.29 24.13,35.56 CN1.32
  Bottom 0.254: v50.8,16.51 48.26,13.97 39.37,13.97 38.1,15.24 v34.29,15.24 | v25.4,7.62 v33.02,7.62 | CN1.32 21.59,35.56 19.05,35.56 17.78,36.83 U$1.32
D0  (via drill 0.61)
  Top 0.254: v68.58,15.24 72.39,19.05 72.39,22.86 73.66,24.13 73.66,45.72 74.93,46.99 74.93,49.53 76.2,50.8 IC3.2 | v57.15,15.24 IC5.11 | v11.43,64.77 11.43,53.34 12.7,52.07 12.7,29.21 13.97,27.94 13.97,17.78 16.51,15.24 v19.05,15.24
  Bottom 0.254: CN1.10 21.59,66.04 19.05,66.04 17.78,64.77 v11.43,64.77 U$1.10 | v68.58,15.24 v57.15,15.24 52.07,15.24 49.53,12.7 39.37,12.7 38.1,13.97 25.4,13.97 24.13,15.24 v19.05,15.24
D1  (via drill 0.61)
  Top 0.254: v58.42,24.13 58.42,7.62 59.69,6.35 IC5.12 | v10.16,60.96 8.89,62.23 U$1.11 | v74.93,40.64 74.93,44.45 76.2,45.72 IC3.4 | v95.25,49.53 93.98,48.26 93.98,45.72 | 93.98,45.72 93.98,43.18 95.25,41.91 | 95.25,41.91 96.52,40.64 IC4.15 | 95.25,36.83 96.52,35.56 IC4.13 | 95.25,36.83 95.25,41.91 | 93.98,45.72 IC4.17 | CN1.11 21.59,60.96 27.94,60.96 v27.94,40.64 | 95.25,36.83 95.25,31.75 96.52,30.48 IC4.11
  Bottom 0.254: v58.42,24.13 59.69,25.4 91.44,25.4 96.52,30.48 IC4.11 | CN1.11 19.05,62.23 17.78,60.96 v10.16,60.96 | IC4.17 IC4.4 | IC4.13 IC4.8 | IC4.15 IC4.6 87.63,40.64 86.36,39.37 76.2,39.37 | 76.2,39.37 v74.93,40.64 | v95.25,49.53 93.98,50.8 IC4.2 | v27.94,40.64 35.56,40.64 36.83,39.37 50.8,39.37 52.07,38.1 63.5,38.1 64.77,39.37 76.2,39.37
D2  (via drill 0.61)
  Top 0.254: v78.74,7.62 78.74,29.21 80.01,30.48 80.01,39.37 | 80.01,39.37 78.74,40.64 IC3.6 | v24.13,73.66 25.4,74.93 v25.4,78.74 | v93.98,83.82 93.98,64.77 96.52,62.23 96.52,54.61 95.25,53.34 95.25,50.8 96.52,49.53 95.25,48.26 v95.25,46.99 | v80.01,45.72 80.01,39.37
  Bottom 0.254: U$1.12 17.78,62.23 19.05,63.5 21.59,63.5 CN1.12 24.13,63.5 v24.13,73.66 | v78.74,7.62 63.5,7.62 62.23,6.35 IC5.13 | v25.4,78.74 29.21,82.55 54.61,82.55 57.15,85.09 92.71,85.09 v93.98,83.82 | v95.25,46.99 88.9,46.99 86.36,44.45 83.82,44.45 82.55,45.72 v80.01,45.72
D3  (via drill 0.61)
  Top 0.254: v10.16,58.42 8.89,59.69 U$1.13 | IC5.15 64.77,19.05 66.04,17.78 66.04,12.7 67.31,11.43 74.93,11.43 74.93,34.29 76.2,35.56 IC3.8 | CN1.13 21.59,58.42 26.67,58.42 v26.67,54.61 | v35.56,31.75 v35.56,54.61 | v31.75,25.4 v31.75,31.75 | v29.21,24.13 27.94,22.86 v27.94,8.89 | v39.37,8.89 43.18,12.7 43.18,15.24 v44.45,16.51
  Bottom 0.254: CN1.13 19.05,59.69 17.78,58.42 v10.16,58.42 | v35.56,54.61 v26.67,54.61 | v31.75,31.75 v35.56,31.75 | v31.75,25.4 30.48,24.13 v29.21,24.13 | v27.94,8.89 v39.37,8.89 | v44.45,16.51 49.53,16.51 50.8,17.78 63.5,17.78 64.77,19.05 IC5.15
D4  (via drill 0.61)
  Top 0.254: v62.23,27.94 IC5.16 | v49.53,62.23 52.07,64.77 v52.07,78.74 | v72.39,82.55 76.2,78.74 76.2,71.12 73.66,68.58 v73.66,53.34 | v69.85,50.8 69.85,44.45 71.12,43.18 v71.12,29.21
  Bottom 0.254: U$1.14 17.78,59.69 19.05,60.96 21.59,60.96 CN1.14 24.13,60.96 36.83,60.96 38.1,62.23 v49.53,62.23 | v62.23,27.94 63.5,29.21 v71.12,29.21 82.55,29.21 83.82,30.48 IC3.11 | v52.07,78.74 55.88,82.55 v72.39,82.55 | v73.66,53.34 74.93,52.07 74.93,50.8 v69.85,50.8
D5  (via drill 0.61)
  Top 0.254: v10.16,55.88 8.89,57.15 U$1.15 | v59.69,36.83 v59.69,30.48 IC5.17 | CN1.15 21.59,55.88 21.59,53.34 17.78,53.34 v17.78,43.18 | v25.4,43.18 26.67,41.91 26.67,34.29 27.94,33.02 v27.94,31.75
  Bottom 0.254: CN1.15 19.05,57.15 17.78,55.88 v10.16,55.88 | v59.69,36.83 78.74,36.83 80.01,35.56 IC3.13 | v17.78,43.18 v25.4,43.18 | v27.94,31.75 29.21,30.48 v59.69,30.48
D6  (via drill 0.61)
  Top 0.254: v71.12,22.86 72.39,24.13 v72.39,40.64 v72.39,53.34 | v55.88,55.88 v55.88,53.34
  Bottom 0.254: U$1.16 17.78,57.15 19.05,58.42 21.59,58.42 CN1.16 49.53,57.15 50.8,55.88 v55.88,55.88 | v71.12,22.86 58.42,22.86 57.15,21.59 IC5.18 | v72.39,40.64 73.66,41.91 82.55,41.91 83.82,40.64 IC3.15 | v55.88,53.34 v72.39,53.34
D7  (via drill 0.61)
  Top 0.254: v10.16,53.34 8.89,54.61 U$1.17 | v57.15,16.51 54.61,19.05 IC5.19 | v82.55,22.86 82.55,44.45 83.82,45.72 IC3.17 | CN1.17 19.05,55.88 19.05,63.5 v29.21,63.5 | v33.02,63.5 34.29,62.23 v34.29,50.8 | v44.45,49.53 v45.72,48.26 | v69.85,43.18 v69.85,20.32
  Bottom 0.254: CN1.17 19.05,54.61 17.78,53.34 v10.16,53.34 | v57.15,16.51 68.58,16.51 71.12,19.05 | 71.12,19.05 74.93,22.86 v82.55,22.86 | v29.21,63.5 v33.02,63.5 | v34.29,50.8 39.37,50.8 40.64,49.53 v44.45,49.53 | v45.72,48.26 46.99,46.99 55.88,46.99 57.15,45.72 69.85,45.72 v69.85,43.18 | v69.85,20.32 71.12,19.05
DBEN1*  (via drill 0.61)
  Top 0.254: v73.66,46.99 73.66,50.8 76.2,53.34 IC3.1 78.74,53.34 78.74,60.96 81.28,63.5 81.28,69.85 82.55,69.85 83.82,68.58 83.82,54.61 82.55,53.34 82.55,52.07 83.82,50.8 IC3.19
  Bottom 0.254: IC2.19 v73.66,46.99
DBEN2*
  Bottom 0.254: IC2.20 69.85,48.26 74.93,48.26 76.2,49.53 86.36,49.53 IC4.1 93.98,53.34 96.52,50.8 IC4.19
E  (via drill 0.61)
  Top 0.254: v48.26,78.74 v48.26,48.26 | v29.21,81.28 26.67,78.74 26.67,73.66 CN1.6
  Bottom 0.254: IC2.13 59.69,48.26 v48.26,48.26 | v48.26,78.74 45.72,81.28 v29.21,81.28 | CN1.6 21.59,71.12 19.05,71.12 17.78,69.85 U$1.6
GND  (via drill 0.61)
  Top 0.762: PAD8.1 PAD7.1 3.81,11.43 PAD6.1 | PAD6.1 C1.2 JP8.1 | U$1.33 v8.89,34.29 11.43,34.29 11.43,29.21 12.7,27.94 v12.7,20.32 | PAD6.1 PAD5.1 | v63.5,33.02 IC2.14 | 90.17,24.13 IC4.10 | 90.17,24.13 95.25,24.13 RESET.3 | 90.17,24.13 RESET.4 88.9,24.13 83.82,19.05 POWER.K 83.82,5.08 77.47,5.08 | 77.47,5.08 IC5.14 v64.77,13.97 | v34.29,25.4 v34.29,27.94 C2.2 | 77.47,5.08 IC3.10 | v96.52,85.09 96.52,83.82 99.06,81.28 U$10.3 | X1.2 X2.2@2 | C4.2 80.01,60.96 82.55,63.5 IC6.2 | PAD1.1 PAD2.1 3.81,90.17 PAD3.1 PAD4.1 7.62,85.09 12.7,80.01 12.7,63.5 15.24,60.96 v15.24,24.13 | JP6.2 JP5.2 JP4.2 JP3.2 JP2.2 JP1.2 | IC7.3 v62.23,62.23
  Bottom 0.762: v8.89,34.29 U$1.33 | C6.2 25.4,15.24 24.13,16.51 12.7,16.51 | 12.7,16.51 7.62,16.51 PAD5.1 | 12.7,16.51 v12.7,20.32 | IC1.7 52.07,33.02 v63.5,33.02 64.77,33.02 67.31,30.48 IC3.10 | C2.2 33.02,35.56 24.13,35.56 CN1.34 CN1.33 | v34.29,25.4 58.42,25.4 59.69,26.67 85.09,26.67 88.9,30.48 IC4.10 | C1.2 16.51,11.43 62.23,11.43 v64.77,13.97 | 95.25,86.36 92.71,88.9 X2.2 X2.2@2 | 95.25,86.36 v96.52,85.09 | 95.25,86.36 99.06,90.17 U$11.3 | X1.2 X1.2@2 44.45,90.17 JP5.2 44.45,92.71 43.18,93.98 12.7,93.98 PAD3.1 | IC6.2 IC6.3 | 80.01,59.69 88.9,59.69 C5.2 | 80.01,59.69 69.85,59.69 C3.2 v62.23,62.23 | 80.01,59.69 C4.2 | IC7.3 IC7.2 59.69,68.58 57.15,71.12 44.45,71.12 JP2.2 | v34.29,27.94 27.94,27.94 24.13,24.13 v15.24,24.13
  pour Bottom: 0,101.6 101.6,101.6 101.6,0 0,0
  pour Top: 0,101.6 101.6,101.6 101.6,0 0,0
HALT*  (via drill 0.61)
  Top 0.254: U$1.3 v10.16,72.39
  Bottom 0.254: v10.16,72.39 CN1.3
LEFT*  (via drill 0.61)
  Top 0.254: v62.23,50.8 62.23,59.69 63.5,60.96 v63.5,64.77 | v85.09,63.5 86.36,64.77 86.36,72.39 87.63,73.66 IC6.13 IC6.12
  Bottom 0.254: IC2.17 v62.23,50.8 | v63.5,64.77 69.85,64.77 71.12,63.5 v85.09,63.5
N$1
  Bottom 0.254: R7.2 80.01,8.89 POWER.A
N$2  (via drill 0.61)
  Top 0.254: JP8.2 R8.1 | v45.72,10.16 45.72,17.78 46.99,19.05 IC5.22
  Bottom 0.254: v45.72,10.16 21.59,10.16 16.51,5.08 JP8.2
N$3  (via drill 0.61)
  Top 0.254: v58.42,91.44 58.42,69.85 57.15,68.58 IC7.1
  Bottom 0.254: v58.42,91.44 60.96,93.98 97.79,93.98 99.06,95.25 U$11.1
N$4
  Top 0.254: C8.1 91.44,83.82 91.44,85.09 99.06,92.71 U$11.2
N$5
  Top 0.254: IC6.1 80.01,69.85 83.82,73.66 83.82,76.2 90.17,82.55 92.71,82.55 92.71,83.82 95.25,86.36 U$10.1 99.06,86.36
N$6
  Top 0.254: C8.2 X2.1
N$7
  Bottom 0.254: C7.1 83.82,83.82 85.09,82.55 97.79,82.55 99.06,83.82 U$10.2
N$8
  Top 0.254: C7.2 X1.1
NMI*
  Bottom 0.254: CN1.4 21.59,73.66 10.16,73.66 8.89,72.39 U$1.4
Q  (via drill 0.61)
  Top 0.254: CN1.7 17.78,69.85 17.78,95.25 16.51,96.52 JP7.1 | v11.43,66.04 11.43,67.31 U$1.7
  Bottom 0.254: v11.43,66.04 17.78,66.04 19.05,67.31 CN1.7
R/W*  (via drill 0.61)
  Top 0.254: v50.8,44.45 49.53,45.72 v49.53,55.88
  Bottom 0.254: v50.8,44.45 IC2.12 | 24.13,55.88 v49.53,55.88 | 24.13,55.88 CN1.18 | 24.13,55.88 19.05,55.88 17.78,54.61 U$1.18
RESET*  (via drill 0.61)
  Top 0.254: RESET.2 90.17,19.05 95.25,19.05 RESET.1 | v10.16,68.58 8.89,69.85 U$1.5 | v60.96,27.94 v60.96,24.13 | v49.53,29.21 48.26,30.48 48.26,44.45 46.99,45.72 v46.99,69.85 | v20.32,78.74 19.05,77.47 19.05,71.12 CN1.5
  Bottom 0.254: CN1.5 19.05,69.85 17.78,68.58 v10.16,68.58 | v60.96,24.13 83.82,24.13 88.9,19.05 RESET.2 | v60.96,27.94 59.69,29.21 v49.53,29.21 | v46.99,69.85 30.48,69.85 21.59,78.74 v20.32,78.74
RIGHT*  (via drill 0.61)
  Top 0.254: IC7.12 IC7.13 64.77,78.74 59.69,83.82 59.69,92.71 58.42,92.71 53.34,87.63 v53.34,39.37 | v68.58,40.64 IC2.18
  Bottom 0.254: v68.58,40.64 54.61,40.64 v53.34,39.37
SCS*
  Bottom 0.254: CN1.36 21.59,30.48 16.51,30.48 15.24,31.75 U$1.36
SLENB*  (via drill 0.61)
  Top 0.254: CN1.40 21.59,25.4 v21.59,17.78
  Bottom 0.254: v21.59,17.78 19.05,17.78 10.16,26.67 U$1.40
SND  (via drill 0.61)
  Top 0.254: v10.16,33.02 8.89,31.75 U$1.35
  Bottom 0.254: CN1.35 19.05,33.02 v10.16,33.02
VCC  (via drill 0.61)
  Top 0.762: v29.21,20.32 C6.1 | v55.88,2.54 31.75,2.54 IC5.1 v31.75,12.7 IC5.28 31.75,21.59 33.02,22.86 33.02,35.56 31.75,36.83 31.75,41.91 | v85.09,55.88 IC3.20 | 67.31,59.69 66.04,58.42 IC2.28 | 67.31,59.69 C3.1 | v82.55,60.96 C4.1 | v10.16,63.5 8.89,64.77 U$1.9 | 31.75,41.91 33.02,40.64 | 33.02,40.64 C2.1 | 31.75,41.91 R1.1 R2.1 R3.1 R4.1 31.75,69.85 34.29,72.39 34.29,77.47 | 33.02,40.64 v34.29,41.91 | IC7.14 IC7.15 v59.69,81.28 | 34.29,77.47 R5.1 | 34.29,81.28 34.29,85.09 R6.1 | 34.29,77.47 34.29,81.28 | v78.74,81.28 78.74,80.01 82.55,76.2 IC6.15 | v15.24,78.74 v15.24,63.5 | v66.04,59.69 67.31,59.69 | v39.37,60.96 38.1,62.23 38.1,77.47 34.29,81.28
  Bottom 0.762: C1.1 R8.2 24.13,12.7 v31.75,12.7 | IC5.28 v29.21,20.32 | R7.1 81.28,19.05 86.36,13.97 86.36,2.54 v55.88,2.54 | IC4.20 C5.1 90.17,60.96 v82.55,60.96 71.12,60.96 C3.1 | C4.1 v85.09,55.88 | CN1.9 19.05,64.77 17.78,63.5 v15.24,63.5 v10.16,63.5 | v34.29,41.91 IC1.14 | IC6.15 IC6.14 | R5.1 44.45,74.93 46.99,77.47 58.42,77.47 59.69,76.2 IC7.15 | v59.69,81.28 v78.74,81.28 | v15.24,78.74 24.13,87.63 R6.1 | v66.04,59.69 64.77,60.96 v39.37,60.96

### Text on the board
Top: Stereo Pak, Version 1.0 | L | R | Copyright ©22 FEB 2010 | http://www.GIMEchip.com/
tValues: Stereo Pak, Version 1.0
